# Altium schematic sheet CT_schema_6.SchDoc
size 277 x 170 mm
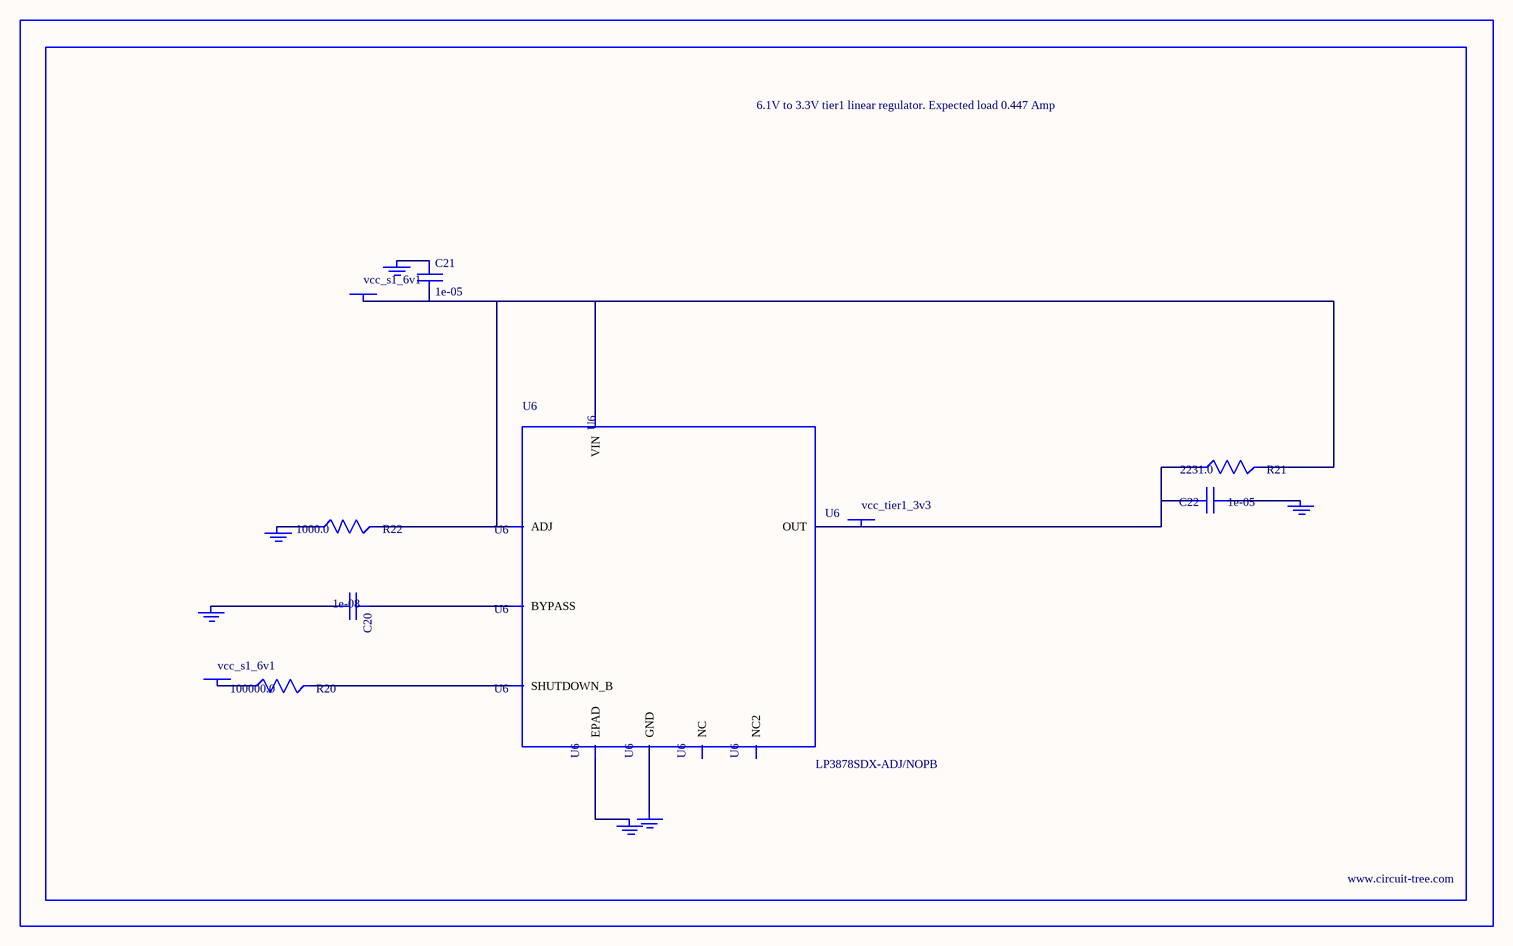
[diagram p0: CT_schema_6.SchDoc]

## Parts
BORDER5  (no value)
C20  1e-08  [C0402]
C21  1e-05  [C1206]
C22  1e-05  [C1210]
GND_INSTANCE_5_0  (no value)
GND_INSTANCE_5_1  (no value)
GND_INSTANCE_5_2  (no value)
GND_INSTANCE_5_3  (no value)
GND_INSTANCE_5_4  (no value)
GND_INSTANCE_5_5  (no value)
POWER_INSTANCE_5_0  vcc_s1_6v1
POWER_INSTANCE_5_1  vcc_s1_6v1
POWER_INSTANCE_5_2  vcc_tier1_3v3
R20  100000.0  [R0603]
R21  2231.0  [R0603]
R22  1000.0  [R0603]
U6  LP3878SDX-ADJ/NOPB  [WSON-8]

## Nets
NetC20_1: C20.1 U6.1(BYPASS)
NetC20_2: C20.2 GND_INSTANCE_5_0.0(GND)
NetC21_1: C21.1 GND_INSTANCE_5_1.0(GND)
NetC21_2: C21.2 POWER_INSTANCE_5_0.0(PWR) R21.2 R22.2 U6.4(VIN) U6.6(ADJ)
NetC22_1: C22.1 GND_INSTANCE_5_2.0(GND)
NetC22_2: C22.2 POWER_INSTANCE_5_2.0(PWR) R21.1 U6.5(OUT)
NetGND_INSTANCE_5_3_0: GND_INSTANCE_5_3.0(GND) R22.1
NetGND_INSTANCE_5_4_0: GND_INSTANCE_5_4.0(GND) U6.PAD(EPAD)
NetGND_INSTANCE_5_5_0: GND_INSTANCE_5_5.0(GND) U6.3(GND)
NetPOWER_INSTANCE_5_1_0: POWER_INSTANCE_5_1.0(PWR) R20.1
NetR20_2: R20.2 U6.8(SHUTDOWN_B)

Not connected (* = marked no-connect by the designer): U6 2(NC) 7(NC2)

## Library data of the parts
BORDER5 = BORDER_PAGE5
C20 = C0402C103K3RAC
C21 = C1206C106K3RACTU
C22 = GRM32DR61E106MA12L
GND_INSTANCE_5_0-GND_INSTANCE_5_5 = GND
POWER_INSTANCE_5_0-POWER_INSTANCE_5_2 = PWR
R20 = RC0603JR-07100KL
R21 = R21
R22 = RC0603JR-071KL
